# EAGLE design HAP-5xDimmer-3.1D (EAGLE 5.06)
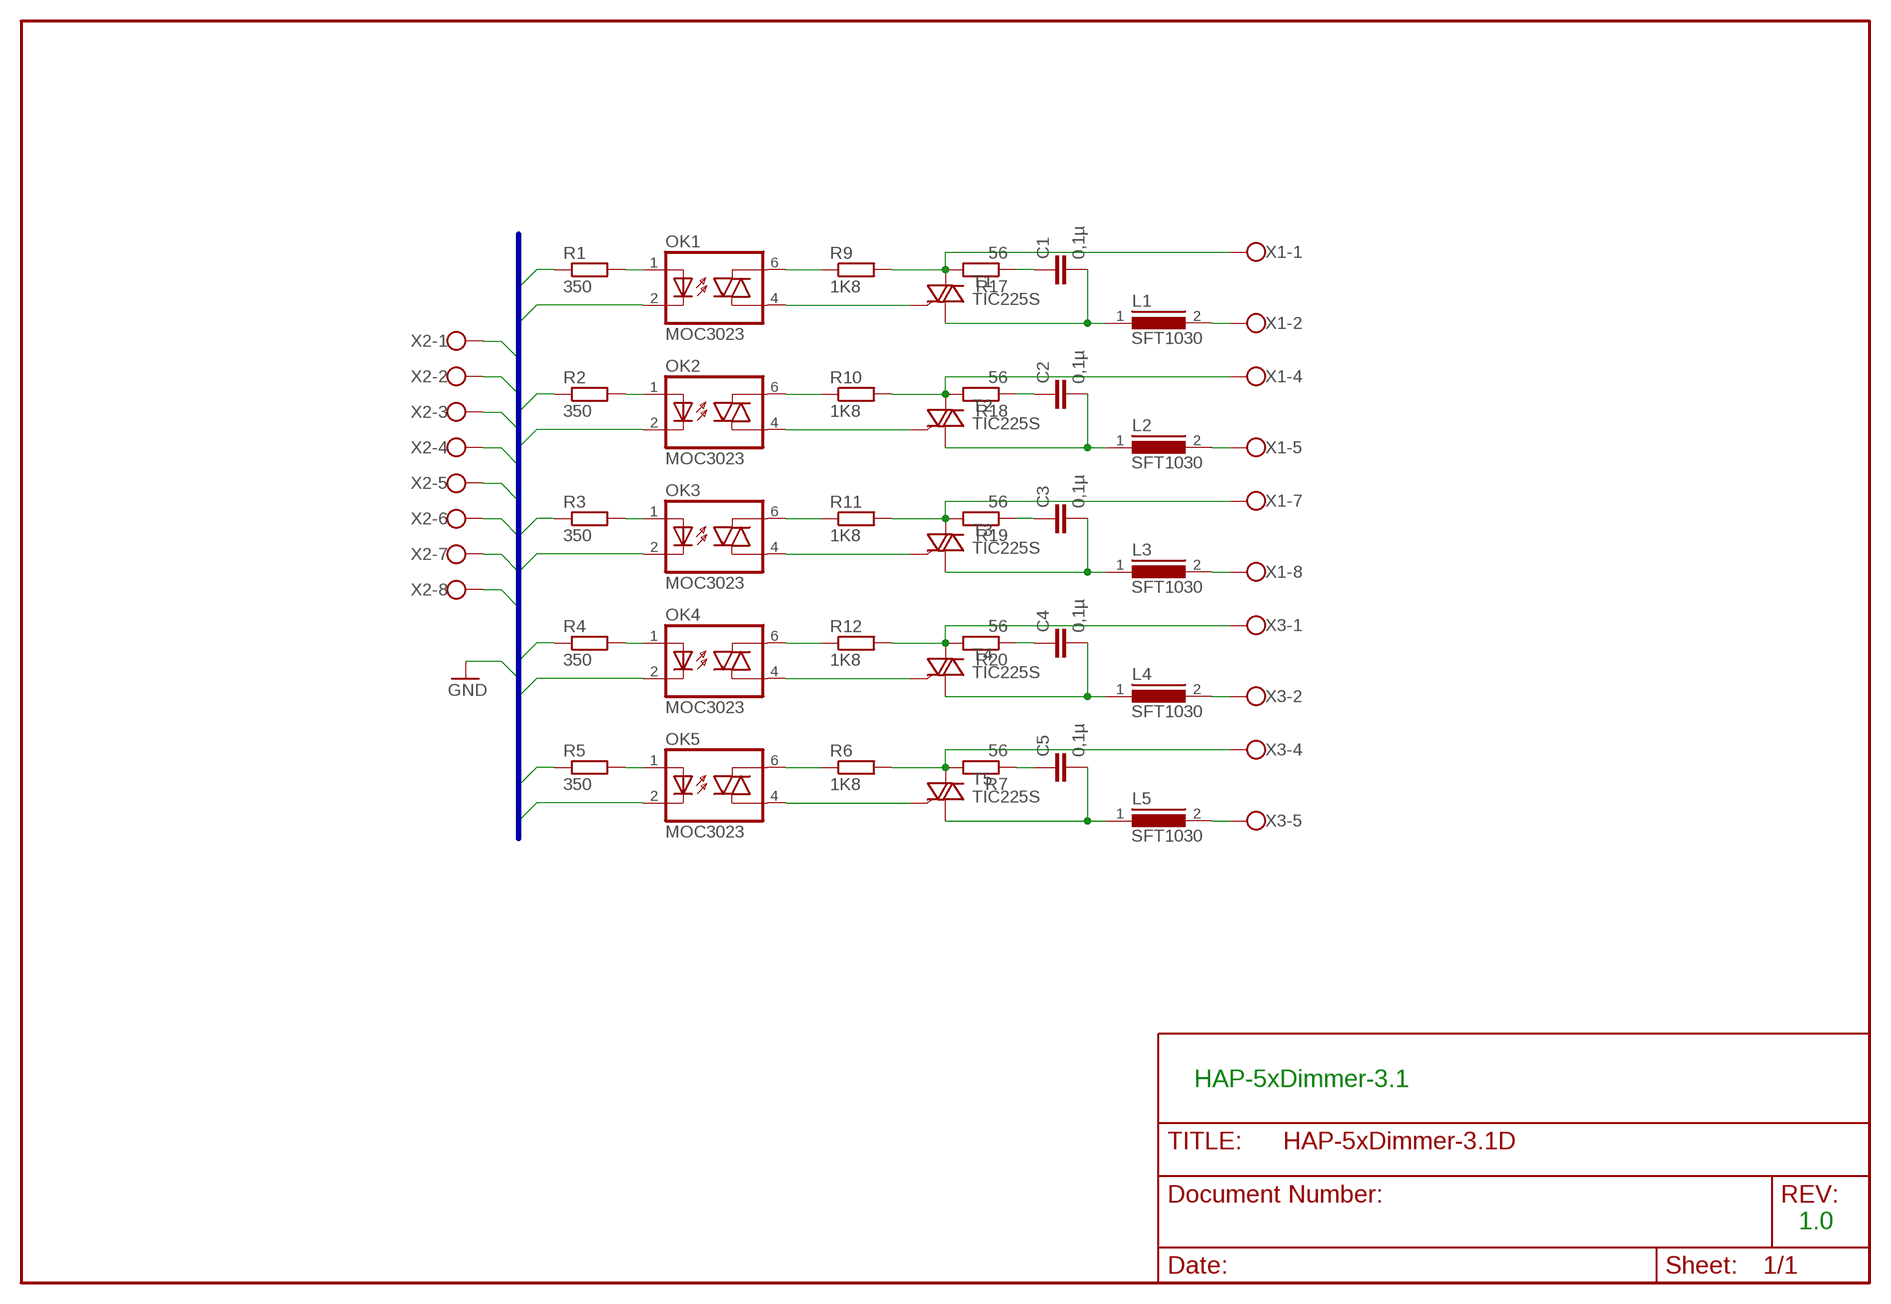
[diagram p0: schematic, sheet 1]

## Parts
C1  0,1µ  C15/8  [C15B8]
C2  0,1µ  C15/8  [C15B8]
C3  0,1µ  C15/8  [C15B8]
C4  0,1µ  C15/8  [C15B8]
C5  0,1µ  C15/8  [C15B8]
L1  SFT1030  [SFT1030]
L2  SFT1030  [SFT1030]
L3  SFT1030  [SFT1030]
L4  SFT1030  [SFT1030]
L5  SFT1030  [SFT1030]
OK1  MOC3023  IL420  [DIL06]
OK2  MOC3023  IL420  [DIL06]
OK3  MOC3023  IL420  [DIL06]
OK4  MOC3023  IL420  [DIL06]
OK5  MOC3023  IL420  [DIL06]
R1  350  R-EU_0204/7  [0204/7]
R2  350  R-EU_0204/7  [0204/7]
R3  350  R-EU_0204/7  [0204/7]
R4  350  R-EU_0204/7  [0204/7]
R5  350  R-EU_0204/7  [0204/7]
R6  1K8  R-EU_0411/3V  [0411V]
R7  56  R-EU_0411/3V  [0411V]
R9  1K8  R-EU_0411/3V  [0411V]
R10  1K8  R-EU_0411/3V  [0411V]
R11  1K8  R-EU_0411/3V  [0411V]
R12  1K8  R-EU_0411/3V  [0411V]
R17  56  R-EU_0411/3V  [0411V]
R18  56  R-EU_0411/3V  [0411V]
R19  56  R-EU_0411/3V  [0411V]
R20  56  R-EU_0411/3V  [0411V]
T1  TIC225S  [TO220DS]
T2  TIC225S  [TO220DS]
T3  TIC225S  [TO220DS]
T4  TIC225S  [TO220DS]
T5  TIC225S  [TO220DS]
X1  W237-08P  [W237-8P]
X2  W237-08P  [W237-8P]
X3  W237-08P  [W237-8P]

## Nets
D0: R1.1 X2.1
D1: R2.1 X2.2
D2: R3.1 X2.3
D3: R4.1 X2.4
D4: R5.1 X2.5
GND: OK1.2(C) OK2.2(C) OK3.2(C) OK4.2(C) OK5.2(C) X2.6 X2.7 X2.8
N$1 [Mains]: C1.2 L1.1 T1.A1
N$2 [Medium]: OK1.4(A1) T1.G
N$3 [Medium]: OK2.4(A1) T2.G
N$4: OK1.1(A) R1.2
N$5 [Medium]: C3.1 R19.1
N$6 [Mains]: L1.2 X1.2
N$7 [Mains]: R9.2 R17.2 T1.A2 X1.1
N$8: OK2.1(A) R2.2
N$9 [Mains]: R10.2 R18.2 T2.A2 X1.4
N$10: OK3.1(A) R3.2
N$11 [Mains]: R11.2 R19.2 T3.A2 X1.7
N$12: OK4.1(A) R4.2
N$14 [Mains]: L2.2 X1.5
N$17 [Mains]: L4.2 X3.2
N$20: OK5.1(A) R5.2
N$21 [Mains]: C2.2 L2.1 T2.A1
N$22 [Medium]: C5.1 R7.1
N$23 [Mains]: C3.2 L3.1 T3.A1
N$24 [Mains]: C5.2 L5.1 T5.A1
N$25 [Mains]: C4.2 L4.1 T4.A1
N$26 [Medium]: OK5.4(A1) T5.G
N$27 [Medium]: OK5.6(A2) R6.1
N$28 [Medium]: OK3.4(A1) T3.G
N$29 [Medium]: OK4.4(A1) T4.G
N$38 [Medium]: OK4.6(A2) R12.1
N$39 [Medium]: OK3.6(A2) R11.1
N$40 [Medium]: OK2.6(A2) R10.1
N$41 [Medium]: OK1.6(A2) R9.1
N$50 [Medium]: C1.1 R17.1
N$51 [Medium]: C2.1 R18.1
N$52 [Medium]: C4.1 R20.1
N$57 [Mains]: R12.2 R20.2 T4.A2 X3.1
N$59 [Mains]: L3.2 X1.8
N$61 [Mains]: R6.2 R7.2 T5.A2 X3.4
N$62 [Mains]: L5.2 X3.5
Unconnected: X1.3 X1.6 X3.3 X3.6 X3.7 X3.8

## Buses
D[0..7],GND

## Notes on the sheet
- HAP-5xDimmer-3.1
- 1.0

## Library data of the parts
C1-C5 = capacitor-wima:C: CAPACITOR
L1-L5 = inductors:SFT1030: INDUCTOR
OK1-OK5 = optocoupler:IL420: SIEMENS OPTO COUPLER
R1-R7 R9-R12 R17-R20 = rcl:R-EU_: RESISTOR, European symbol
T1-T5 = triac:TIC225S: TRIAC
X1-X3 = con-wago-508:W237-08P: WAGO SREW CLAMP

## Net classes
1 Mains: width 2.184 mm, clearance 0.508 mm
2 Medium: width 0.813 mm, clearance 0.508 mm

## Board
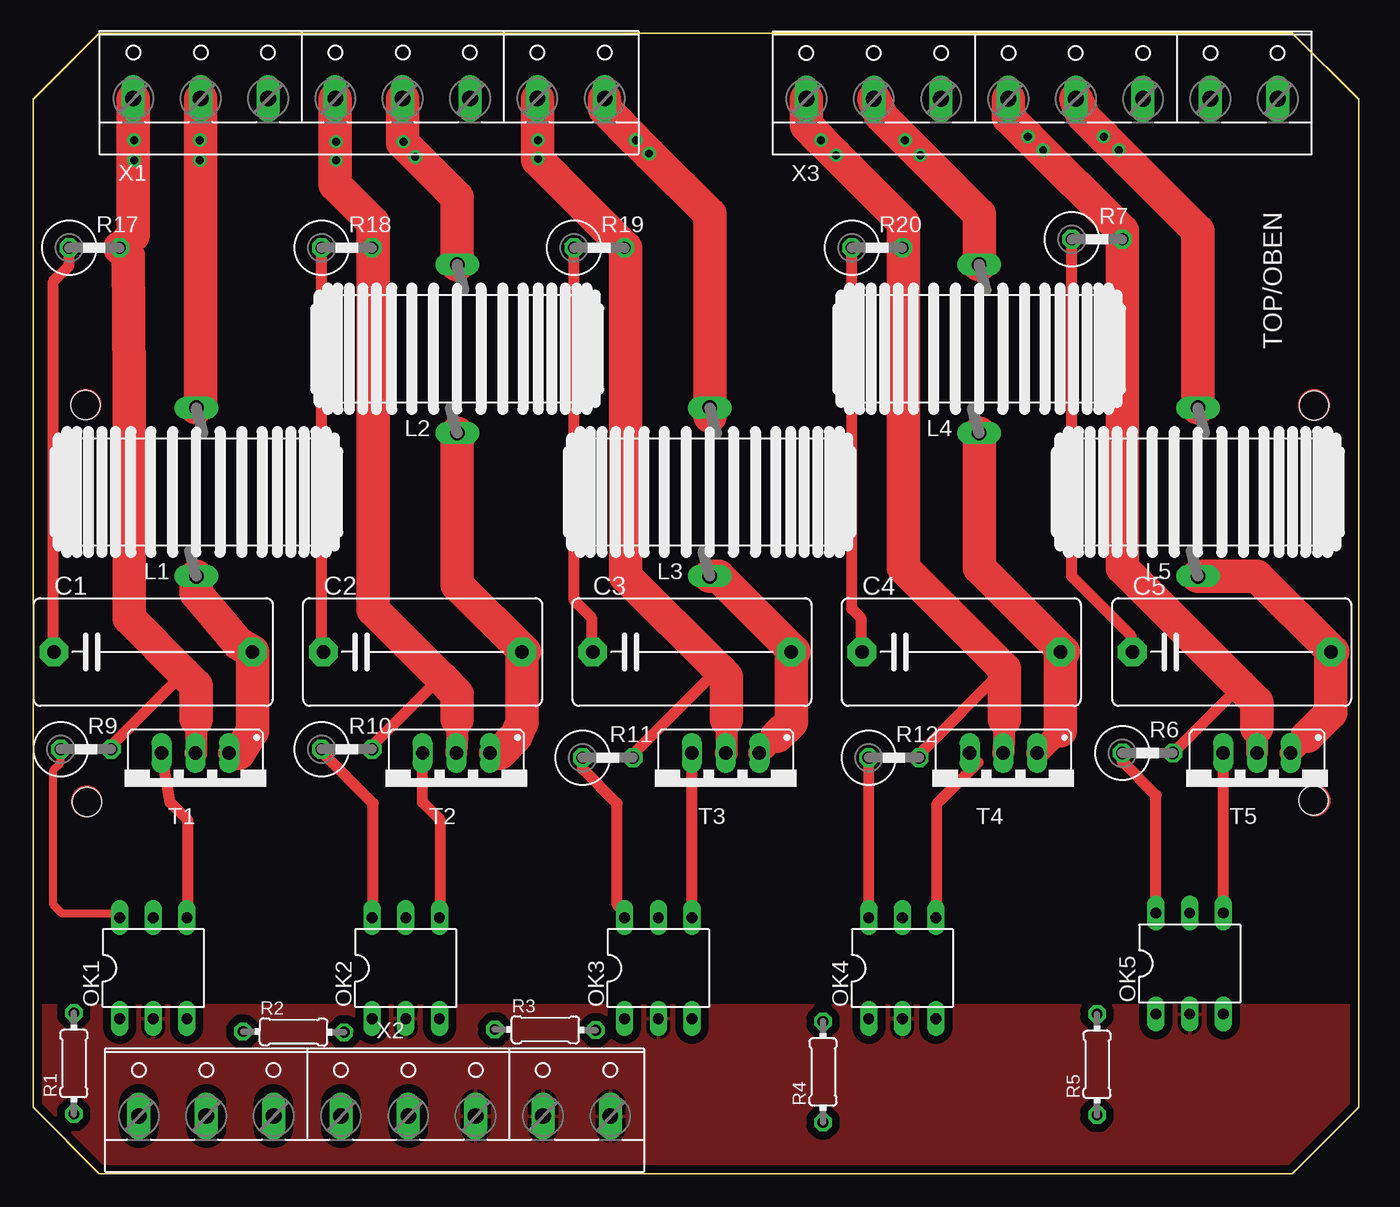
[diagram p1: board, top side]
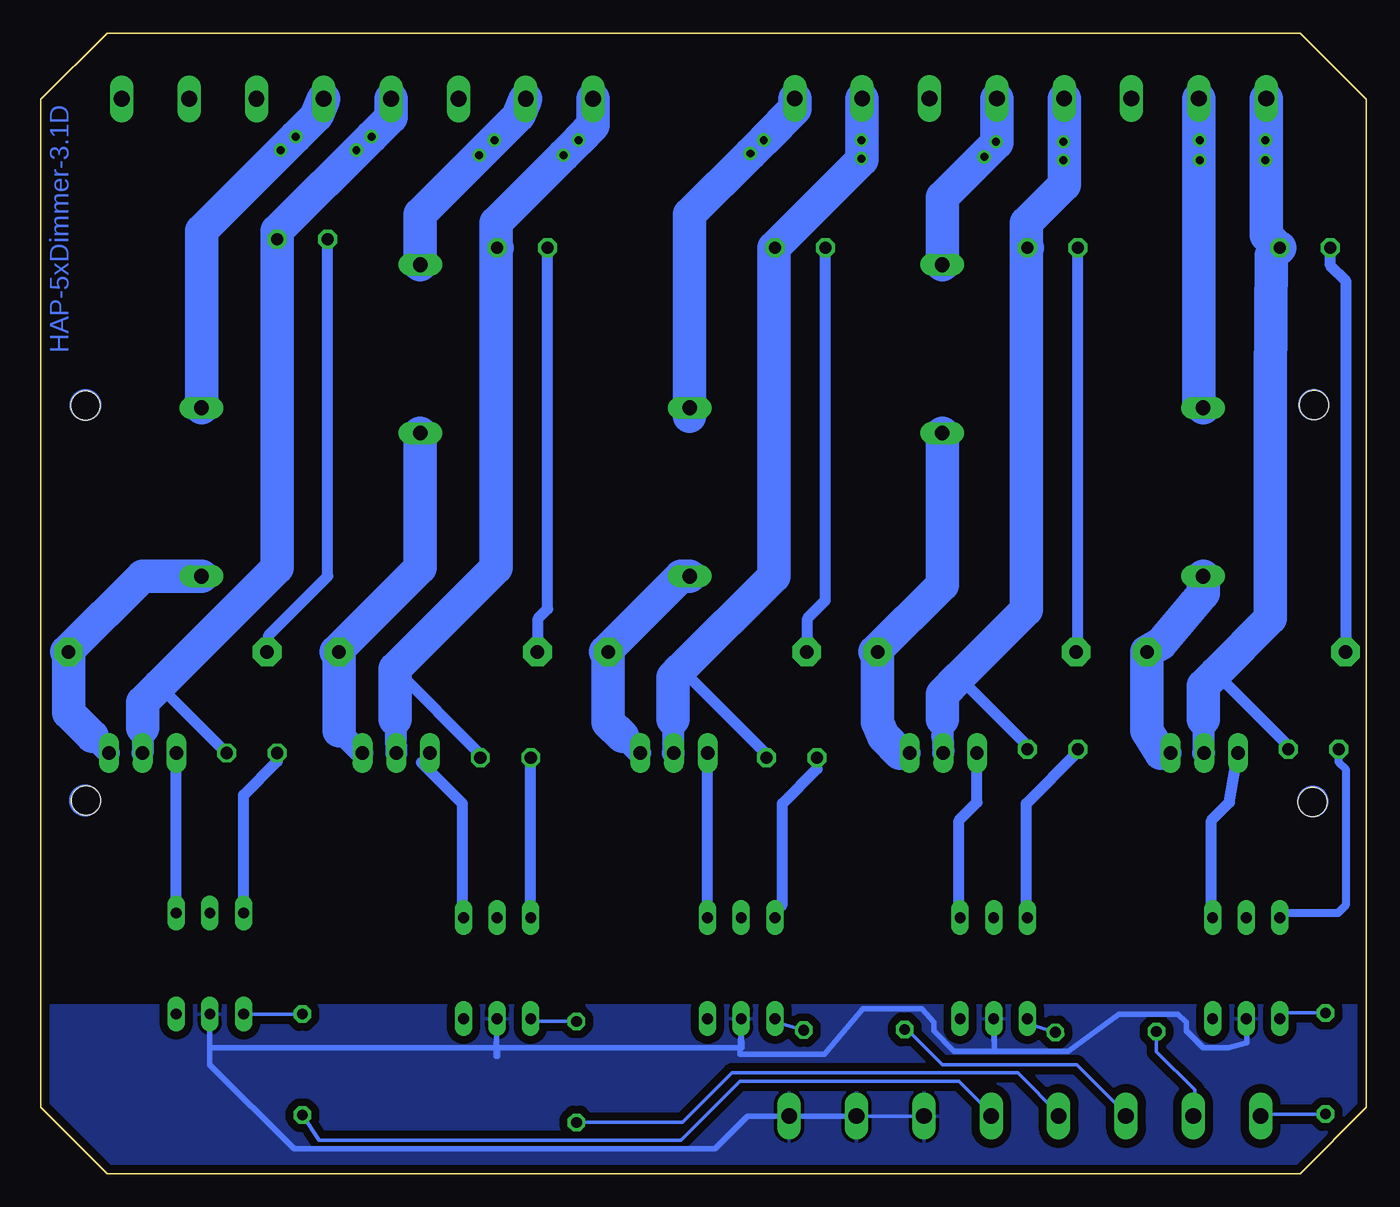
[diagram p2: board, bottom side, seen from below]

Size 100 x 86.01 mm. Coordinates in mm from the lower left corner, seen from the top.
Outline: 5,86.01 0.01,81.01 0,5 5,0 95,0.01
Outline: 95,86.01 100,81.01
Outline: 100,5.01 95,0.01
Outline: 100,81 100,5.01
Outline: 5,86.01 95,86.01
Copper layers (1*16): Top 0.035mm / dielectric 1.5mm / Bottom 0.035mm
Design rules "default": minimum track width 10mil, minimum drill 24mil, track to track 8mil, track to pad 8mil, pad to pad 8mil, via to via 8mil, smd to smd 8mil, copper to edge 10mil, drill to drill 8mil, minimum pad ring 10mil, minimum via ring 8mil, stop-mask expansion 4mil, vias tented up to drill 0mil, thermal gap 10mil
Holes 2.2 mm at 4.07,28.03 96.6,28.14 96.62,57.94 3.96,57.98

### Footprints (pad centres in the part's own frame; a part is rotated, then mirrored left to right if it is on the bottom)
C15B8 = drill 1.016 pad 2.159 octagon: 1 -7.493,0; 2 7.493,0
SFT1030 = drill 1.118 long: 1 -6.35,0; 2 6.35,0
DIL06 = drill 0.813 long: 1 -2.54,-3.81; 2 0,-3.81; 3 2.54,-3.81; 4 2.54,3.81; 5 0,3.81; 6 -2.54,3.81
0204/7 = drill 0.813 octagon: 1 -3.81,0; 2 3.81,0
0411V = drill 0.914 octagon: 1 -2.54,0; 2 1.27,0
TO220DS = drill 1.016 long: A1 -2.54,-2.54; A2 0,-2.54; G 2.54,-2.54
W237-8P = drill 1.194 long: 1 -17.78,-0.635; 2 -12.7,-0.635; 3 -7.62,-0.635; 4 -2.54,-0.635; 5 2.54,-0.635; 6 7.62,-0.635; 7 12.7,-0.635; 8 17.78,-0.635

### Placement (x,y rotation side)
C1  9.06,39.34 0 top
C2  29.38,39.34 0 top
C3  49.7,39.34 0 top
C4  70.02,39.34 0 top
C5  90.42,39.34 0 top
L1  12.32,51.41 90 top
L2  32,62.2 90 top
L3  51.05,51.41 90 top
L4  71.37,62.2 90 top
L5  87.88,51.41 90 top
OK1  9.06,15.5 0 top
OK2  28.11,15.5 0 top
OK3  47.16,15.5 0 top
OK4  65.58,15.5 0 top
OK5  87.25,15.85 0 top
R1  3.08,8.31 90 top
R2  19.65,10.69 359.5 top
R3  38.64,10.85 359.6 top
R4  59.59,7.67 90 top
R5  80.26,8.23 90 top
R6  84.71,31.72 0 top
R7  80.9,70.46 0 top
R9  4.62,32.01 0 top
R10  24.3,32.01 0 top
R11  43.99,31.37 0 top
R12  65.58,31.37 0 top
R17  5.25,69.82 0 top
R18  24.3,69.82 0 top
R19  43.35,69.82 0 top
R20  64.31,69.82 0 top
T1  12.24,29.18 180 top
T2  31.92,29.18 180 top
T3  52.24,29.18 180 top
T4  73.2,29.18 180 top
T5  92.33,29.18 180 top
X1  25.34,81.71 0 top
X2  25.76,4.98 0 top
X3  76.12,81.69 0 top

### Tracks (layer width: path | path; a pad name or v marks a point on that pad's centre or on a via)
D0
  Bottom 0.254: X2.1 7.95,4.34 7.79,4.5 R1.1
D1
  Bottom 0.254: R2.1 15.84,9.21 12.95,6.32 12.95,4.42 13.03,4.34 X2.2
D2
  Bottom 0.254: R3.1 34.83,11.05 32,8.23 21.84,8.23 18.03,4.42 18.11,4.34 X2.3
D3
  Bottom 0.254: R4.1 51.61,3.86 47.88,7.59 26.29,7.59 23.11,4.42 23.19,4.34 X2.4
D4
  Bottom 0.254: R5.1 78.99,2.51 51.69,2.51 47.24,6.96 30.73,6.96 28.19,4.42 28.27,4.34 X2.5
GND
  Bottom 0.254: X2.7 38.43,4.34 38.35,4.42 38.28,4.34 X2.6 | 42.87,4.34 43.43,3.78 43.43,4.42
  Bottom 0.406: 87.25,9.5 OK5.2 | 65.66,9.5 65.58,11.48 OK4.2 65.58,10.69 65.66,9.5 | 65.66,9.5 65.66,8.86 65.53,8.86 65.53,9.5 | 65.53,9.5 65.53,9.62 | 65.66,9.5 65.53,9.5 | 65.66,9.5 87.25,9.5 | 65.66,9.5 47.11,9.5 47.16,11.48 | 47.16,11.48 47.16,10.69 47.24,8.99 40.89,8.99 37.97,12.42 33.52,12.42 32.64,11.4 32.64,10.77 31.11,9.24 28.06,9.24 | 47.16,11.48 OK3.2 | 28.06,9.24 28.06,10.77 28.11,11.48 OK2.2 28.11,10.69 28.06,9.24 | 28.06,9.24 22.48,9.24 18.67,12.04 14.22,12.04 13.59,11.4 13.59,10.77 12.32,9.5 10.41,9.5 9.01,9.88 9.01,11.15 9.06,12.12 OK1.2 | X2.8 43.51,4.34 43.43,4.42 43.36,4.34 42.87,4.34 | 42.87,4.34 X2.7 | 42.87,4.34 46.68,4.34 49.15,1.88 80.9,1.88 87.25,8.23 87.25,9.5
  pour Bottom (isolate 0.61): 0.25,12.67 99.31,12.67 99.95,11.4 99.95,5.05 94.87,-0.03 4.06,-0.03 -0.38,4.42 -0.38,11.4
  pour Top (isolate 0.61): 0.25,12.67 99.31,12.67 99.95,11.4 99.95,5.05 94.87,-0.03 4.06,-0.03 -0.38,4.42 -0.38,11.4
N$1
  Bottom 1.676: T1.A1 15.49,31.72
  Bottom 2.54: L1.1 12.32,43.79 15.49,39.98 C1.2 16.55,33.42 15.49,31.72
N$2
  Bottom 0.813: T1.G 10.33,27.99 11.68,26.64 11.68,19.66 11.6,19.74 OK1.4
N$3
  Bottom 0.813: 30.65,19.74 30.73,19.66 30.65,19.58 OK2.4 30.65,19.1 30.73,19.02 30.73,26.64 29.38,27.99 T2.G
N$4
  Bottom 0.254: 6.52,12.12 OK1.1 | R1.2 6.52,12.12 | 6.52,12.12 6.6,12.04
N$5
  Bottom 0.61: C3.1 42.16,39.34
  Bottom 0.813: R19.1 40.81,43.23 42.16,41.88 42.16,39.34
N$6
  Bottom 2.54: X1.2 12.64,58.08 L1.2
N$7
  Bottom 0.813: R9.2 5.89,32.28 11.36,37.75
  Bottom 1.676: T1.A2 12.32,31.72 12.32,34.26
  Bottom 2.54: X1.1 7.56,70.78 6.6,69.82 R17.2 7.16,69.27 7.24,59.66 7.24,41.88 11.36,37.75 12.32,36.8 12.32,34.26
N$8
  Bottom 0.254: OK2.1 25.57,11.48 25.65,11.4 25.54,11.29 R2.2
N$9
  Bottom 0.813: R10.2 25.57,32.28 30.73,37.44
  Bottom 1.676: T2.A2 32,32.99 32,34.26
  Bottom 2.54: X1.4 22.8,74.58 25.65,71.73 25.65,69.82 | 25.65,69.82 R18.2 | 25.65,69.82 25.65,42.52 30.73,37.44 32,36.17 32,34.26
N$10
  Bottom 0.254: 44.65,11.45 44.62,11.48 OK3.1 | 44.65,11.45 R3.2 | 44.65,11.45 44.7,11.4
N$11
  Bottom 0.813: R11.2 45.26,31.64 51.69,38.07
  Bottom 1.676: T3.A2 52.32,31.72 52.32,34.26
  Bottom 2.54: 44.7,69.82 R19.2 | X1.7 38.04,76.48 44.7,69.82 | 44.7,69.82 44.7,45.06 51.69,38.07 52.32,37.44 52.32,34.26
N$12
  Bottom 0.254: 63.04,11.48 OK4.1 | R4.2 63.04,11.48 | 63.04,11.48 63.12,11.4
N$14
  Bottom 2.54: X1.5 27.88,77.75 32,73.63 L2.2
N$17
  Bottom 2.54: X3.2 63.95,79.78 71.37,72.36 L4.2
N$20
  Bottom 0.254: R5.2 OK5.1
N$21
  Bottom 1.676: T2.A1 35.18,31.72
  Bottom 2.54: L2.1 32,44.42 37.08,39.34 C2.2 36.87,34.05 36.45,32.99 35.18,31.72
N$22
  Bottom 0.813: C5.1 82.8,40.61 78.36,45.06 R7.1
N$23
  Bottom 1.676: T3.A1 54.86,31.72 56.13,32.99
  Bottom 2.54: L3.1 51.69,45.06 57.4,39.34 C3.2 57.19,34.05 56.13,32.99
N$24
  Bottom 1.676: T5.A1 96.14,32.99
  Bottom 2.54: L5.1 92.33,45.06 98.04,39.34 C5.2 97.91,34.77 96.14,32.99
N$25
  Bottom 1.676: T4.A1 75.82,31.72 77.51,33.42
  Bottom 2.54: L4.1 71.37,45.69 77.72,39.34 C4.2 77.51,33.42
N$26
  Bottom 0.813: OK5.4 T5.G
N$27
  Bottom 0.813: R6.1 82.17,31.09 84.71,28.55 OK5.6
N$28
  Bottom 0.813: OK3.4 49.7,19.58 49.78,19.66 49.7,19.74 T3.G
N$29
  Bottom 0.813: T4.G 71.29,31.01 68.2,27.91 68.2,19.66 68.12,19.58 OK4.4
N$30
  Top 0.813: 9.7,31.72 10.33,27.99 11.68,26.64 11.68,19.66 11.6,19.74 11.6,19.31
N$31
  Top 0.813: 30.65,19.74 30.73,19.66 30.65,19.58 30.65,19.1 30.73,19.02 30.73,26.64 29.38,27.99 29.38,31.72
N$32
  Top 0.813: 49.7,19.31 49.7,19.58 49.78,19.66 49.7,19.74 49.7,31.72
N$33
  Top 0.813: 63.04,19.31 63.04,19.58 63.12,19.66 63.04,19.74 63.04,31.37
N$34
  Top 0.813: 41.45,31.37 41.45,30.53 44.07,27.91 44.07,20.29 44.7,19.66 44.62,19.58 44.62,19.31
N$35
  Top 0.813: 21.76,32.01 21.76,31.8 25.65,27.91 25.65,19.02 25.57,19.1 25.57,19.31
N$36
  Top 0.406: 6.6,19.66 6.52,19.58
  Top 0.61: 2.08,32.01 2.08,31.01 1.52,30.45 1.52,20.29 2.16,19.66 6.6,19.66 | 6.52,19.58 6.52,19.31
  Top 0.813: 6.6,19.66 6.52,19.74
N$37
  Top 0.813: 70.66,31.72 71.29,31.01 68.2,27.91 68.2,19.66 68.12,19.58 68.12,19.31
N$38
  Bottom 0.813: OK4.6 63.04,19.58 63.12,19.66 63.04,19.74 R12.1
N$39
  Bottom 0.813: R11.1 41.45,30.53 44.07,27.91 44.07,20.29 44.7,19.66 44.62,19.58 OK3.6
N$40
  Bottom 0.813: R10.1 21.76,31.8 25.65,27.91 25.65,19.02 25.57,19.1 OK2.6
N$41
  Bottom 0.406: 6.6,19.66 6.52,19.58
  Bottom 0.61: R9.1 2.08,31.01 1.52,30.45 1.52,20.29 2.16,19.66 6.6,19.66 | 6.52,19.58 OK1.6
  Bottom 0.813: 6.6,19.66 6.52,19.74
N$42
  Top 1.676: 54.78,31.72 54.86,31.72 56.13,32.99
  Top 2.54: 51.05,45.06 51.69,45.06 57.4,39.34 57.19,39.34 57.19,34.05 56.13,32.99
N$43
  Top 1.676: 75.74,31.72 75.82,31.72 77.51,33.42
  Top 2.54: 71.37,55.85 71.37,45.69 77.72,39.34 77.51,39.34 77.51,33.42
N$44
  Top 0.61: 2.16,39.34 2.08,39.9
  Top 0.813: 2.71,69.82 2.71,68.47 1.52,67.28 1.52,39.98 2.16,39.34 1.57,39.34
N$45
  Top 0.61: 21.89,39.34 21.84,39.34 21.76,39.42
  Top 0.813: 21.76,39.42 21.76,69.82
N$46
  Top 0.61: 42.16,39.34 42.21,39.34
  Top 0.813: 40.81,69.82 40.81,43.23 42.16,41.88 42.16,39.34
N$47
  Top 1.676: 34.46,31.72 35.18,31.72
  Top 2.54: 32,55.85 32,44.42 37.08,39.34 36.87,39.34 36.87,34.05 36.45,32.99 35.18,31.72
N$48
  Top 1.676: 15.49,31.72 14.78,31.72
  Top 2.54: 12.32,45.06 12.32,43.79 15.49,39.98 16.55,39.34 16.55,33.42 15.49,31.72
N$49
  Top 0.61: 62.48,39.34 62.53,39.34
  Top 0.813: 61.77,69.82 61.77,42.6 62.48,41.88 62.48,39.34
N$50
  Bottom 0.61: 2.16,39.34 2.08,39.9
  Bottom 0.813: R17.1 2.71,68.47 1.52,67.28 1.52,39.98 2.16,39.34 C1.1
N$51
  Bottom 0.61: C2.1 21.84,39.34 21.76,39.42
  Bottom 0.813: 21.76,39.42 R18.1
N$52
  Bottom 0.61: C4.1 62.48,39.34
  Bottom 0.813: R20.1 61.77,42.6 62.48,41.88 62.48,39.34
N$53
  Top 2.54: 12.64,81.08 12.63,81.07 12.63,74.04 12.64,58.08 12.32,57.76
N$54
  Top 0.813: 5.89,32.01 5.89,32.28 11.36,37.75
  Top 1.676: 12.24,31.72 12.32,31.72 12.32,34.26
  Top 2.54: 7.56,81.08 7.56,70.78 6.6,69.82 6.52,69.82 7.16,69.27 7.24,59.66 7.24,41.88 11.36,37.75 12.32,36.8 12.32,34.26
N$55
  Top 0.813: 25.57,32.01 25.57,32.28 30.73,37.44
  Top 1.676: 31.92,31.72 32,32.99 32,34.26
  Top 2.54: 22.8,81.08 22.8,74.58 25.65,71.73 25.65,69.82 | 25.65,69.82 25.57,69.82 | 25.65,69.82 25.65,42.52 30.73,37.44 32,36.17 32,34.26
N$56
  Top 0.813: 45.26,31.37 45.26,31.64 51.69,38.07
  Top 1.676: 52.24,31.72 52.32,31.72 52.32,34.26
  Top 2.54: 44.7,69.82 44.62,69.82 | 38.04,81.08 38.04,76.48 44.7,69.82 | 44.7,69.82 44.7,45.06 51.69,38.07 52.32,37.44 52.32,34.26
N$57  (via drill 0.6 pad 0.9)
  Top 0.813: R12.2 66.85,31.64 73.28,38.07
  Top 1.676: 73.28,34.26 T4.A2
  Top 2.54: X3.1 58.34,79.05 v59.43,77.95 v60.58,76.81 65.66,71.73 65.66,69.82 | 65.66,69.82 R20.2 | 65.66,69.82 65.66,45.69 73.28,38.07 73.28,34.26
  Bottom 0.813: R12.2 66.85,31.64 73.28,38.07
  Bottom 1.676: 73.28,34.26 T4.A2
  Bottom 2.54: X3.1 58.34,79.05 v59.43,77.95 v60.58,76.81 65.66,71.73 65.66,69.82 | 65.66,69.82 R20.2 | 65.66,69.82 65.66,45.69 73.28,38.07 73.28,34.26
N$58
  Top 2.54: 27.88,81.08 27.88,77.75 32,73.63 32,68.55
N$59  (via drill 0.6 pad 0.9)
  Top 2.54: X1.8 43.12,80.29 v45.46,77.95 v46.48,76.93 51.05,72.36 51.05,57.12
  Bottom 2.54: X1.8 43.12,80.29 v45.46,77.95 v46.48,76.93 51.05,72.36 L3.2 51.05,57.12
N$60
  Top 2.54: 63.42,81.05 63.95,79.78 71.37,72.36 71.37,68.55
N$61  (via drill 0.6 pad 0.9)
  Top 0.813: R6.2 91.06,36.8
  Top 1.676: 92.33,33.63 T5.A2
  Top 2.54: X3.4 73.58,79.68 v75.05,78.2 82.17,71.09 82.17,45.69 91.06,36.8 92.33,35.53 92.33,33.63
  Bottom 0.813: R6.2 91.06,36.8
  Bottom 1.676: 92.33,33.63 T5.A2
  Bottom 2.54: X3.4 73.58,79.68 v75.05,78.2 82.17,71.09 R7.2 82.17,45.69 91.06,36.8 92.33,35.53 92.33,33.63
N$62  (via drill 0.6 pad 0.9)
  Top 2.54: X3.5 79.19,79.78 v80.77,78.2 87.88,71.09 L5.2
  Bottom 2.54: X3.5 79.19,79.78 v80.77,78.2 87.88,71.09 L5.2
N$63
  Top 0.813: 82.93,39.34 82.8,40.61 78.36,45.06 78.36,70.46
N$64
  Top 1.676: 94.87,31.72 96.14,32.99
  Top 2.54: 87.88,45.06 92.33,45.06 98.04,39.34 97.91,39.34 97.91,34.77 96.14,32.99
N$66
  Top 0.813: 89.79,19.66 89.79,31.72
N$67
  Top 0.813: 82.17,31.72 82.17,31.09 84.71,28.55 84.71,19.66
N$68  (via drill 0.6 pad 0.9)
  other vias: 7.62,77.95
N$69  (via drill 0.6 pad 0.9)
  other vias: 12.57,77.95
N$70  (via drill 0.6 pad 0.9)
  other vias: 22.86,77.82
N$71  (via drill 0.6 pad 0.9)
  other vias: 27.94,77.82
N$72  (via drill 0.6 pad 0.9)
  other vias: 38.1,76.55
N$73  (via drill 0.6 pad 0.9)
  other vias: 65.78,77.95
N$74  (via drill 0.6 pad 0.9)
  other vias: 81.91,77.19
N$75  (via drill 0.6 pad 0.9)
  other vias: 76.2,77.19
N$76  (via drill 0.6 pad 0.9)
  other vias: 66.93,76.81
N$77  (via drill 0.6 pad 0.9)
  other vias: 38.1,77.95
N$78  (via drill 0.6 pad 0.9)
  other vias: 28.83,76.68
N$79  (via drill 0.6 pad 0.9)
  other vias: 22.86,76.42
N$80  (via drill 0.6 pad 0.9)
  other vias: 12.57,76.42
N$81  (via drill 0.6 pad 0.9)
  other vias: 7.62,76.42
(copper drawn outside any net)
  shapes: Bottom circle x4, Top circle x4

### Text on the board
Bottom: HAP-5xDimmer-3.1D
tPlace: TOP/OBEN
tStop: TOP/OBEN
